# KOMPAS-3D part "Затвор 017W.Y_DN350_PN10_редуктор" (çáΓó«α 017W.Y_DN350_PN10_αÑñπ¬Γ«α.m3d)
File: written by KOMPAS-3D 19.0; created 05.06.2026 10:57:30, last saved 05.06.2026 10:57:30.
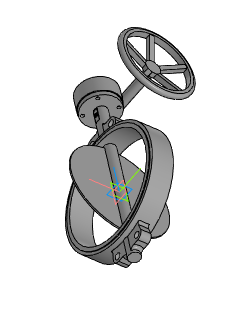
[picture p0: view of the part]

Document properties: Автор: Энергия; Полное имя файла: ..\..\..\3d для проектировщиков\x.x Тип 017W.Y(S) Затвор дисковый поворотный межфланцевый\Затвор 017W.Y(S)_DN50-DN1200_редуктор\Затвор 017W.Y_DN350_PN10_редуктор.a3d

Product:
- Part/product: Затвор 017W.Y_DN350_PN10_редуктор
    Масса: 38.6131

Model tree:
1. Операция без истории:1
